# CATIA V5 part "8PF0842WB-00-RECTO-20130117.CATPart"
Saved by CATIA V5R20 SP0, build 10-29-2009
Part number: 8PF0842WB-00-RECTO-20130117
Revision: ANY
Definition: UNKNOWN
Nomenclature: 8PF0842WB-00-RECTO-20130117
Source: Unknown
Bounding box of the stored display mesh (mm): x 1824.755 to 2024.755, y 1399.61 to 1403.61, z 0 to 8
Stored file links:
  C:\Users\Utente\Desktop\IO LAVORO\3D X SITO CF\CUMSA\3D files PF\PF 0842WB\8PF0842WB-00-RECTO-20130117.CATPart
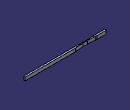
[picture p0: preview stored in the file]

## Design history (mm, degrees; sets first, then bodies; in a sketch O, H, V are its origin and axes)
Body1 "Cortar-Extruir1" (main body)
  Solid1: solid without history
